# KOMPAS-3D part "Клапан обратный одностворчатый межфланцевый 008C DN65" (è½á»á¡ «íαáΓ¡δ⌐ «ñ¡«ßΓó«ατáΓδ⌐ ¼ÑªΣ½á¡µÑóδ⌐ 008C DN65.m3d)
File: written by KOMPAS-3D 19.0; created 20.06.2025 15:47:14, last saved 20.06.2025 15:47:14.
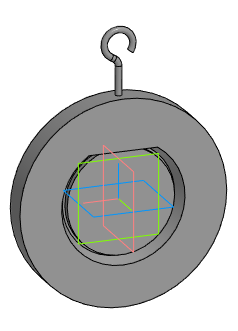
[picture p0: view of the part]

Document properties: Полное имя файла: E:\Dendor Работа Сачек\3D для проектировщиков\5.1 Тип 008C. Клапан обратный одностворчатый межфланцевый\stp_Клапан обратный одностворчатый межфланцевый 008C\Клапан обратный одностворчатый межфланцевый 008C DN65.m3d

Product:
- Part/product: Клапан обратный одностворчатый межфланцевый 008C DN65

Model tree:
1. Операция без истории:1  (labels: Клапан обратный одностворчатый межфланцевый 008C DN65)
